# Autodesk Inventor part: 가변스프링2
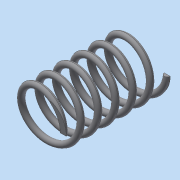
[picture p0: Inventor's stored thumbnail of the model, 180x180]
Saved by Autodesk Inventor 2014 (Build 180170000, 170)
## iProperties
Created: 2023-01
Part Number: 가변스프링2
Material: 스테인레스 스틸
Document SubType Name: Modeling
Designer: dg
Density: 8.08 g/cm^3
Appearance: 반연마
Mass: 7.92893 g
Surface Area: 20.018 cm^2
Volume: 0.981303 cm^3
Author: dg
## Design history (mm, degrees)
sketch "스케치1"
  geometry: L1 (8.5, 0)-(0, 0); L2 (0, 0)-(0, 17); L3 (0, 17)-(8.5, 17); C1 r 1 at (8.5, 0)
  constraints: 6 end point, 1 centre point, 1 coincident, 1 horizontal, 1 parallel, 1 vertical, 1 vertical alignment
  dimensions: "d0" = 2 diameter of C1; "d1" = 17 distance of L1.end L2.end (derived); "d2" = 17 diameter of L1.start L2
feature "코일1" sketch "스케치1" pitch "d3" = 10; turns "d5" = 6; dims "d4" = 17 (= d1), "d6" = 0, angle "d7" = 90 deg, angle "d8" = 90 deg, "d9" = 0, "d10" = 0
node "작업 평면1"
node "작업 평면2"
feature "분할1"
feature "분할2"
node "솔리드1"
other parameters: "d11" = 90 deg, "d12" = 90 deg
